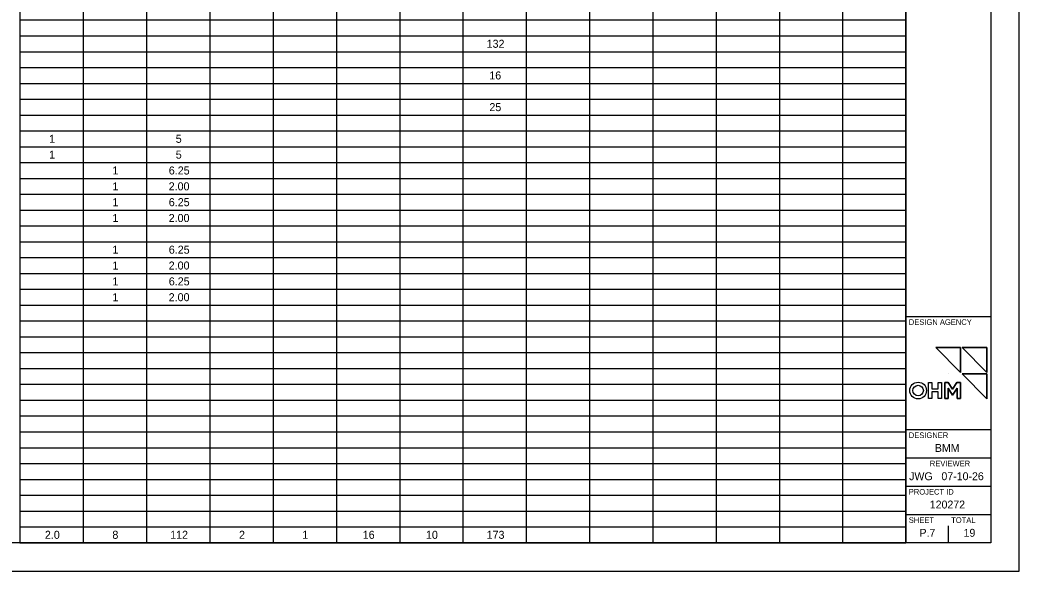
# Model space of a CAD drawing. Extents: x 0 to 34, y 0 to 22.
# Drawn here: x 16.33 to 34, y 0 to 9.74 of the extents above; entities that cross this region are included whole.
import ezdxf

# ---------------------------------------------------------------- set-up
doc = ezdxf.new("R2010")
doc.units = 0
for name, color, linetype in [('Default', 7, 'Continuous'), ('SH_Border', 7, 'Continuous'), ('SH_Cut_Line', 7, 'Continuous'), ('SH_Data', 7, 'Continuous'), ('TX_P_Misc', 7, 'Continuous')]:
    doc.layers.add(name, color=color, linetype=linetype)

msp = doc.modelspace()

# ---------------------------------------------------------------- linework, layer by layer
at = {"layer": 'Default'}
for points in [[(32.966, 3.948), (32.966, 3.51), (32.53, 3.948)], [(33.433, 3.948), (33.433, 3.51), (32.997, 3.948)], [(33.433, 3.483), (33.433, 3.045), (32.997, 3.483)], [(32.397, 3.333), (32.457, 3.333), (32.457, 3.22), (32.571, 3.22), (32.571, 3.333), (32.631, 3.333), (32.631, 3.052), (32.571, 3.052), (32.571, 3.166), (32.457, 3.166), (32.457, 3.052), (32.397, 3.052)], [(32.9, 3.335), (32.963, 3.335), (32.963, 3.052), (32.903, 3.052), (32.903, 3.233), (32.824, 3.108), (32.745, 3.233), (32.745, 3.052), (32.685, 3.052), (32.685, 3.335), (32.748, 3.335), (32.824, 3.216)]]:
    msp.add_lwpolyline(points, close=True, dxfattribs=at)
at = {"layer": 'SH_Border'}
for p, q in [((32, 0.5), (32, 21.5)), ((32, 4.5), (33.5, 4.5)), ((32, 2.5), (33.5, 2.5)), ((32, 2), (33.5, 2)), ((32, 1.5), (33.5, 1.5)), ((32, 1), (33.5, 1))]:
    msp.add_line(p, q, dxfattribs=at)
msp.add_lwpolyline([(1.5, 21.5), (33.5, 21.5), (33.5, 0.5), (1.5, 0.5)], close=True, dxfattribs=at)
at = {"layer": 'SH_Cut_Line'}
msp.add_lwpolyline([(0, 0), (34, 0), (34, 22), (0, 22)], close=True, dxfattribs=at)
at = {"layer": 'SH_Data'}
for p, q in [((16.325, 10.58), (16.325, 9.74)), ((17.445, 10.58), (17.445, 9.74)), ((18.565, 10.58), (18.565, 9.74)), ((19.684, 10.58), (19.684, 9.74)), ((20.804, 10.58), (20.804, 9.74)), ((21.923, 10.58), (21.923, 9.74)), ((23.043, 10.58), (23.043, 9.74)), ((24.163, 10.58), (24.163, 9.74)), ((25.282, 10.58), (25.282, 9.74)), ((26.402, 10.58), (26.402, 9.74)), ((27.522, 10.58), (27.522, 9.74)), ((28.641, 10.58), (28.641, 9.74)), ((29.761, 10.58), (29.761, 9.74)), ((30.88, 10.58), (30.88, 9.74)), ((32, 10.58), (32, 9.74)), ((16.325, 9.74), (24.163, 9.74)), ((16.325, 9.74), (16.325, 9.18)), ((17.445, 9.74), (17.445, 9.18)), ((18.565, 9.74), (18.565, 9.18)), ((19.684, 9.74), (19.684, 9.18)), ((20.804, 9.74), (20.804, 9.18)), ((21.923, 9.74), (21.923, 9.18)), ((23.043, 9.74), (23.043, 9.18)), ((24.163, 9.74), (25.282, 9.74)), ((24.163, 9.74), (24.163, 9.18)), ((25.282, 9.74), (27.522, 9.74)), ((25.282, 9.74), (25.282, 9.18)), ((26.402, 9.74), (26.402, 9.18)), ((27.522, 9.74), (30.88, 9.74)), ((27.522, 9.74), (27.522, 9.18)), ((28.641, 9.74), (28.641, 9.18)), ((29.761, 9.74), (29.761, 9.18)), ((30.88, 9.74), (32, 9.74)), ((30.88, 9.74), (30.88, 9.18)), ((32, 9.74), (32, 9.18)), ((16.325, 9.46), (24.163, 9.46)), ((24.163, 9.46), (25.282, 9.46)), ((25.282, 9.46), (27.522, 9.46)), ((27.522, 9.46), (30.88, 9.46)), ((30.88, 9.46), (32, 9.46)), ((16.325, 9.18), (24.163, 9.18)), ((16.325, 9.18), (16.325, 8.34)), ((17.445, 9.18), (17.445, 8.34)), ((18.565, 9.18), (18.565, 8.34)), ((19.684, 9.18), (19.684, 8.34)), ((20.804, 9.18), (20.804, 8.34)), ((21.923, 9.18), (21.923, 8.34)), ((23.043, 9.18), (23.043, 8.34)), ((24.163, 9.18), (25.282, 9.18)), ((24.163, 9.18), (24.163, 8.34)), ((25.282, 9.18), (27.522, 9.18)), ((25.282, 9.18), (25.282, 8.34)), ((26.402, 9.18), (26.402, 8.34)), ((27.522, 9.18), (30.88, 9.18)), ((27.522, 9.18), (27.522, 8.34)), ((28.641, 9.18), (28.641, 8.34)), ((29.761, 9.18), (29.761, 8.34)), ((30.88, 9.18), (32, 9.18)), ((30.88, 9.18), (30.88, 8.34)), ((32, 9.18), (32, 8.34)), ((16.325, 8.9), (24.163, 8.9)), ((24.163, 8.9), (25.282, 8.9)), ((25.282, 8.9), (27.522, 8.9)), ((27.522, 8.9), (30.88, 8.9)), ((30.88, 8.9), (32, 8.9)), ((16.325, 8.62), (24.163, 8.62)), ((24.163, 8.62), (25.282, 8.62)), ((25.282, 8.62), (27.522, 8.62)), ((27.522, 8.62), (30.88, 8.62)), ((30.88, 8.62), (32, 8.62)), ((16.325, 8.34), (24.163, 8.34)), ((16.325, 8.34), (16.325, 7.78)), ((17.445, 8.34), (17.445, 7.78)), ((18.565, 8.34), (18.565, 7.78)), ((19.684, 8.34), (19.684, 7.78)), ((20.804, 8.34), (20.804, 7.78)), ((21.923, 8.34), (21.923, 7.78)), ((23.043, 8.34), (23.043, 7.78)), ((24.163, 8.34), (25.282, 8.34)), ((24.163, 8.34), (24.163, 7.78)), ((25.282, 8.34), (27.522, 8.34)), ((25.282, 8.34), (25.282, 7.78)), ((26.402, 8.34), (26.402, 7.78)), ((27.522, 8.34), (30.88, 8.34)), ((27.522, 8.34), (27.522, 7.78)), ((28.641, 8.34), (28.641, 7.78)), ((29.761, 8.34), (29.761, 7.78)), ((30.88, 8.34), (32, 8.34)), ((30.88, 8.34), (30.88, 7.78)), ((32, 8.34), (32, 7.78)), ((16.325, 8.06), (24.163, 8.06)), ((24.163, 8.06), (25.282, 8.06)), ((25.282, 8.06), (27.522, 8.06)), ((27.522, 8.06), (30.88, 8.06)), ((30.88, 8.06), (32, 8.06)), ((16.325, 7.78), (24.163, 7.78)), ((16.325, 7.78), (16.325, 6.94)), ((17.445, 7.78), (17.445, 6.94)), ((18.565, 7.78), (18.565, 6.94)), ((19.684, 7.78), (19.684, 6.94)), ((20.804, 7.78), (20.804, 6.94)), ((21.923, 7.78), (21.923, 6.94)), ((23.043, 7.78), (23.043, 6.94)), ((24.163, 7.78), (25.282, 7.78)), ((24.163, 7.78), (24.163, 6.94)), ((25.282, 7.78), (27.522, 7.78)), ((25.282, 7.78), (25.282, 6.94)), ((26.402, 7.78), (26.402, 6.94)), ((27.522, 7.78), (30.88, 7.78)), ((27.522, 7.78), (27.522, 6.94)), ((28.641, 7.78), (28.641, 6.94)), ((29.761, 7.78), (29.761, 6.94)), ((30.88, 7.78), (32, 7.78)), ((30.88, 7.78), (30.88, 6.94)), ((32, 7.78), (32, 6.94)), ((16.325, 7.5), (24.163, 7.5)), ((24.163, 7.5), (25.282, 7.5)), ((25.282, 7.5), (27.522, 7.5)), ((27.522, 7.5), (30.88, 7.5)), ((30.88, 7.5), (32, 7.5)), ((16.325, 7.22), (24.163, 7.22)), ((24.163, 7.22), (25.282, 7.22)), ((25.282, 7.22), (27.522, 7.22)), ((27.522, 7.22), (30.88, 7.22)), ((30.88, 7.22), (32, 7.22)), ((16.325, 6.94), (24.163, 6.94)), ((16.325, 6.94), (16.325, 6.38)), ((17.445, 6.94), (17.445, 6.38)), ((18.565, 6.94), (18.565, 6.38)), ((19.684, 6.94), (19.684, 6.38)), ((20.804, 6.94), (20.804, 6.38)), ((21.923, 6.94), (21.923, 6.38)), ((23.043, 6.94), (23.043, 6.38)), ((24.163, 6.94), (25.282, 6.94)), ((24.163, 6.94), (24.163, 6.38)), ((25.282, 6.94), (27.522, 6.94)), ((25.282, 6.94), (25.282, 6.38)), ((26.402, 6.94), (26.402, 6.38)), ((27.522, 6.94), (30.88, 6.94)), ((27.522, 6.94), (27.522, 6.38)), ((28.641, 6.94), (28.641, 6.38)), ((29.761, 6.94), (29.761, 6.38)), ((30.88, 6.94), (32, 6.94)), ((30.88, 6.94), (30.88, 6.38)), ((32, 6.94), (32, 6.38)), ((16.325, 6.66), (24.163, 6.66)), ((24.163, 6.66), (25.282, 6.66)), ((25.282, 6.66), (27.522, 6.66)), ((27.522, 6.66), (30.88, 6.66)), ((30.88, 6.66), (32, 6.66)), ((16.325, 6.38), (24.163, 6.38)), ((16.325, 6.38), (16.325, 0.5)), ((17.445, 6.38), (17.445, 0.5)), ((18.565, 6.38), (18.565, 0.5)), ((19.684, 6.38), (19.684, 0.5)), ((20.804, 6.38), (20.804, 0.5)), ((21.923, 6.38), (21.923, 0.5)), ((23.043, 6.38), (23.043, 0.5)), ((24.163, 6.38), (25.282, 6.38)), ((24.163, 6.38), (24.163, 0.5)), ((25.282, 6.38), (27.522, 6.38)), ((25.282, 6.38), (25.282, 0.5)), ((26.402, 6.38), (26.402, 0.5)), ((27.522, 6.38), (30.88, 6.38)), ((27.522, 6.38), (27.522, 0.5)), ((28.641, 6.38), (28.641, 0.5)), ((29.761, 6.38), (29.761, 0.5)), ((30.88, 6.38), (32, 6.38)), ((30.88, 6.38), (30.88, 0.5)), ((32, 6.38), (32, 0.5)), ((16.325, 6.1), (24.163, 6.1)), ((24.163, 6.1), (25.282, 6.1)), ((25.282, 6.1), (27.522, 6.1)), ((27.522, 6.1), (30.88, 6.1)), ((30.88, 6.1), (32, 6.1)), ((16.325, 5.82), (24.163, 5.82)), ((24.163, 5.82), (25.282, 5.82)), ((25.282, 5.82), (27.522, 5.82)), ((27.522, 5.82), (30.88, 5.82)), ((30.88, 5.82), (32, 5.82)), ((16.325, 5.54), (24.163, 5.54)), ((24.163, 5.54), (25.282, 5.54)), ((25.282, 5.54), (27.522, 5.54)), ((27.522, 5.54), (30.88, 5.54)), ((30.88, 5.54), (32, 5.54)), ((16.325, 5.26), (24.163, 5.26)), ((24.163, 5.26), (25.282, 5.26)), ((25.282, 5.26), (27.522, 5.26)), ((27.522, 5.26), (30.88, 5.26)), ((30.88, 5.26), (32, 5.26)), ((16.325, 4.98), (24.163, 4.98)), ((24.163, 4.98), (25.282, 4.98)), ((25.282, 4.98), (27.522, 4.98)), ((27.522, 4.98), (30.88, 4.98)), ((30.88, 4.98), (32, 4.98)), ((16.325, 4.7), (24.163, 4.7)), ((24.163, 4.7), (25.282, 4.7)), ((25.282, 4.7), (27.522, 4.7)), ((27.522, 4.7), (30.88, 4.7)), ((30.88, 4.7), (32, 4.7)), ((16.325, 4.42), (24.163, 4.42)), ((24.163, 4.42), (25.282, 4.42)), ((25.282, 4.42), (27.522, 4.42)), ((27.522, 4.42), (30.88, 4.42)), ((30.88, 4.42), (32, 4.42)), ((16.325, 4.14), (24.163, 4.14)), ((24.163, 4.14), (25.282, 4.14)), ((25.282, 4.14), (27.522, 4.14)), ((27.522, 4.14), (30.88, 4.14)), ((30.88, 4.14), (32, 4.14)), ((16.325, 3.86), (24.163, 3.86)), ((24.163, 3.86), (25.282, 3.86)), ((25.282, 3.86), (27.522, 3.86)), ((27.522, 3.86), (30.88, 3.86)), ((30.88, 3.86), (32, 3.86)), ((16.325, 3.58), (24.163, 3.58)), ((24.163, 3.58), (25.282, 3.58)), ((25.282, 3.58), (27.522, 3.58)), ((27.522, 3.58), (30.88, 3.58)), ((30.88, 3.58), (32, 3.58)), ((32.75, 3.5), (32.75, 3.5)), ((16.325, 3.3), (24.163, 3.3)), ((24.163, 3.3), (25.282, 3.3)), ((25.282, 3.3), (27.522, 3.3)), ((27.522, 3.3), (30.88, 3.3)), ((30.88, 3.3), (32, 3.3)), ((16.325, 3.02), (24.163, 3.02)), ((24.163, 3.02), (25.282, 3.02)), ((25.282, 3.02), (27.522, 3.02)), ((27.522, 3.02), (30.88, 3.02)), ((30.88, 3.02), (32, 3.02)), ((16.325, 2.74), (24.163, 2.74)), ((24.163, 2.74), (25.282, 2.74)), ((25.282, 2.74), (27.522, 2.74)), ((27.522, 2.74), (30.88, 2.74)), ((30.88, 2.74), (32, 2.74)), ((16.325, 2.46), (24.163, 2.46)), ((24.163, 2.46), (25.282, 2.46)), ((25.282, 2.46), (27.522, 2.46)), ((27.522, 2.46), (30.88, 2.46)), ((30.88, 2.46), (32, 2.46)), ((16.325, 2.18), (24.163, 2.18)), ((24.163, 2.18), (25.282, 2.18)), ((25.282, 2.18), (27.522, 2.18)), ((27.522, 2.18), (30.88, 2.18)), ((30.88, 2.18), (32, 2.18)), ((16.325, 1.9), (24.163, 1.9)), ((24.163, 1.9), (25.282, 1.9)), ((25.282, 1.9), (27.522, 1.9)), ((27.522, 1.9), (30.88, 1.9)), ((30.88, 1.9), (32, 1.9)), ((16.325, 1.62), (24.163, 1.62)), ((24.163, 1.62), (25.282, 1.62)), ((25.282, 1.62), (27.522, 1.62)), ((27.522, 1.62), (30.88, 1.62)), ((30.88, 1.62), (32, 1.62)), ((16.325, 1.34), (24.163, 1.34)), ((24.163, 1.34), (25.282, 1.34)), ((25.282, 1.34), (27.522, 1.34)), ((27.522, 1.34), (30.88, 1.34)), ((30.88, 1.34), (32, 1.34)), ((16.325, 1.06), (24.163, 1.06)), ((24.163, 1.06), (25.282, 1.06)), ((25.282, 1.06), (27.522, 1.06)), ((27.522, 1.06), (30.88, 1.06)), ((30.88, 1.06), (32, 1.06)), ((16.325, 0.78), (24.163, 0.78)), ((24.163, 0.78), (25.282, 0.78)), ((25.282, 0.78), (27.522, 0.78)), ((27.522, 0.78), (30.88, 0.78)), ((30.88, 0.78), (32, 0.78)), ((32.75, 0.5), (32.75, 0.8)), ((32.375, 0.675), (32.375, 0.675)), ((16.325, 0.5), (24.163, 0.5)), ((24.163, 0.5), (25.282, 0.5)), ((25.282, 0.5), (27.522, 0.5)), ((27.522, 0.5), (30.88, 0.5)), ((30.88, 0.5), (32, 0.5))]:
    msp.add_line(p, q, dxfattribs=at)
at = {"layer": 'TX_P_Misc'}
for p, q in [((32.745, 3.052), (32.745, 3.233)), ((32.745, 3.233), (32.824, 3.108)), ((32.824, 3.108), (32.903, 3.233)), ((32.903, 3.233), (32.903, 3.052))]:
    msp.add_line(p, q, dxfattribs=at)
for points in [[(32.53, 3.948), (32.966, 3.51), (32.966, 3.948), (32.53, 3.948)], [(32.997, 3.948), (33.433, 3.51), (33.433, 3.948), (32.997, 3.948)], [(32.997, 3.483), (33.433, 3.045), (33.433, 3.483), (32.997, 3.483)], [(32.824, 3.216), (32.748, 3.335), (32.685, 3.335), (32.685, 3.052), (32.745, 3.052)], [(32.903, 3.052), (32.963, 3.052), (32.963, 3.335), (32.9, 3.335), (32.824, 3.216)]]:
    msp.add_lwpolyline(points, dxfattribs=at)
msp.add_lwpolyline([(32.397, 3.333), (32.457, 3.333), (32.457, 3.22), (32.571, 3.22), (32.571, 3.333), (32.631, 3.333), (32.631, 3.052), (32.571, 3.052), (32.571, 3.166), (32.457, 3.166), (32.457, 3.052), (32.397, 3.052)], close=True, dxfattribs=at)
for radius in [0.148, 0.148, 0.0927, 0.0927]:
    msp.add_circle((32.215, 3.19), radius, dxfattribs=at)

# ---------------------------------------------------------------- texts
at = {"layer": 'SH_Data'}
for s, height, p in [('132', 0.1417, (24.581, 9.249)), ('16', 0.1417, (24.628, 8.689)), ('25', 0.1417, (24.63, 8.129)), ('1', 0.142, (16.841, 7.569)), ('5', 0.142, (19.081, 7.569)), ('1', 0.142, (16.841, 7.289)), ('5', 0.142, (19.081, 7.289)), ('1', 0.142, (17.961, 7.009)), ('6.25', 0.1417, (18.958, 7.009)), ('1', 0.142, (17.961, 6.729)), ('2.00', 0.1417, (18.956, 6.729)), ('1', 0.142, (17.961, 6.449)), ('6.25', 0.1417, (18.958, 6.449)), ('1', 0.142, (17.961, 6.169)), ('2.00', 0.1417, (18.956, 6.169)), ('1', 0.142, (17.961, 5.609)), ('6.25', 0.1417, (18.958, 5.609)), ('1', 0.142, (17.961, 5.329)), ('2.00', 0.1417, (18.956, 5.329)), ('1', 0.142, (17.961, 5.049)), ('6.25', 0.1417, (18.958, 5.049)), ('1', 0.142, (17.961, 4.769)), ('2.00', 0.1417, (18.956, 4.769)), ('DESIGN AGENCY', 0.1, (32.05, 4.35)), ('DESIGNER', 0.1, (32.05, 2.35)), ('BMM', 0.14, (32.511, 2.105)), ('REVIEWER', 0.1, (32.422, 1.85)), ('JWG', 0.14, (32.056, 1.605)), ('07-10-26', 0.14, (32.627, 1.605)), ('PROJECT ID', 0.1, (32.05, 1.35)), ('120272', 0.14, (32.421, 1.105)), ('SHEET', 0.1, (32.05, 0.85)), ('TOTAL', 0.1, (32.8, 0.85)), ('2.0', 0.1417, (16.766, 0.569)), ('8', 0.142, (17.96, 0.569)), ('112', 0.1417, (18.982, 0.569)), ('2', 0.142, (20.2, 0.569)), ('1', 0.142, (21.32, 0.569)), ('16', 0.1417, (22.389, 0.569)), ('10', 0.1417, (23.508, 0.569)), ('173', 0.1417, (24.581, 0.569)), ('P.7', 0.14, (32.239, 0.605)), ('19', 0.14, (33.019, 0.605))]:
    msp.add_text(s, height=height, dxfattribs=at).set_placement(p)

doc.saveas('drawing.dxf')
